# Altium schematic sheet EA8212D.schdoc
size 127 x 101 mm
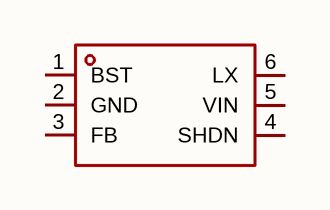
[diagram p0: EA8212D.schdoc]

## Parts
U?  ea8212d  [SOT-23-6_L2.9-W1.6-P0.95-LS2.8-BL]  (value not drawn)

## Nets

Not connected (* = marked no-connect by the designer): U? 1(BST) 2(GND) 3(FB) 4(SHDN) 5(VIN) 6(LX)

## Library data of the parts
U? = ea8212d: 功能类型:降压型;工作电压:4.5V~23V;输出电压:600mV~8V;输出电流:2A;输出类型:可调;; Manufacturer: everanalog(申风); AddInBom: yes; ModelId: 18da8f6c14a34920b3e136b5c401a119; ModelName: SOT-23-6_L2.9-W1.6-H1.5-LS2.8-P0.95; ModelTransform: 110.236,113.364,0,90,0,0,0.0005,0.0005,0; Function: 降压型; Output Current: 2A; Frequency - Switching: 850kHz; Synchronous Rectifier: 是; Number of Outputs: 1; Topology: 降压式; Quiescent Current: 300uA; Switch tube (built-in/external): 内置; Output Type: 可调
